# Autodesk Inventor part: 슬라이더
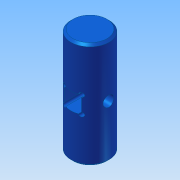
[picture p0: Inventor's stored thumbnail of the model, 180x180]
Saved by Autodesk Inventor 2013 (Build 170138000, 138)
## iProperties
Company: 한국ATC센터
Created: 2015-04
Part Number: 슬라이더
Document SubType Name: Modeling
Designer: KYOUNG IL JANG
Density: 7.85 g/cm^3
Material: 강
Mass: 88.0136 g
Surface Area: 38.9014 cm^2
Volume: 11.2119 cm^3
Author: KYOUNG IL JANG
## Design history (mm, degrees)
sketch "스케치1"
  geometry: C1 r 9 at (0, 0); 1 further point
  constraints: 1 centre point, 1 coincident
  dimensions: "d0" = 18 diameter of C1
extrude "돌출1" new body sketch "스케치1" stored distance "d1" = 50; taper "d2" = 0 deg
node "작업 평면1"
sketch "스케치3"
  geometry: L1 (4, 25)-(-4, 25); L2 (-4, 25)-(-4, -25); L3 (-4, -25)-(4, -25); L4 (4, -25)-(4, 25); 3 further points
  constraints: 8 end point, 2 midpoint, 2 parallel, 1 horizontal, 1 horizontal alignment, 1 perpendicular, 1 vertical alignment
  dimensions: "d5" = 8 distance of L1.start L1.end; "d6" = 50 distance of L1.end L2.end
extrude "돌출3" cut sketch "스케치3" stored distance "d7" = 8; taper "d8" = 0 deg
sketch "스케치4"
  geometry: 5 further points
hole "구멍1" sketch "스케치4" at (4, 4), (-4, 4), (-4, -4), (4, -4) diameter "d9" = 2; stored, may be unused: countersink angle "d13" = 90 deg, drill point angle "d15" = 118 deg; dims "d10" = 6, "d11" = 4, "d12" = 2, "d14" = 8
node "작업 평면2"
sketch "스케치5"
  geometry: 1 further point
hole "구멍2" sketch "스케치5" at (0, 0) diameter "d16" = 5; stored, may be unused: countersink angle "d20" = 90 deg, drill point angle "d22" = 118 deg; dims "d17" = 6, "d18" = 4, "d19" = 2, "d21" = 8
chamfer "모따기1" distance "d23" = 1; stored, may be unused: second distance "d24" = 2, angle "d25" = 45 deg
node "솔리드1"
mirror "대칭1"
